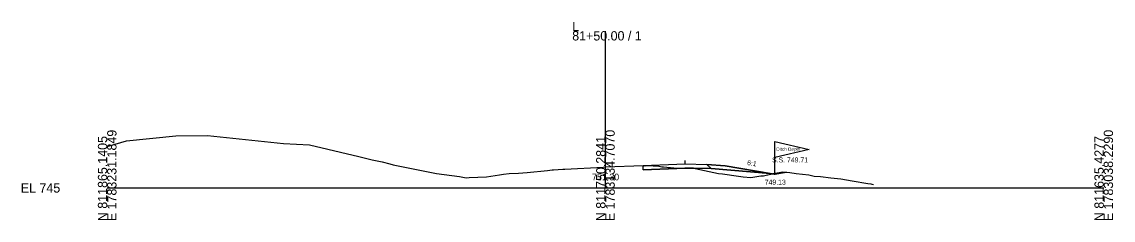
# Model space of a CAD drawing. Extents: x -26 to 7903, y -10 to 9573.
# Drawn here: x 4974.3 to 5302.8, y 2490.3 to 2549.9 of the extents above; entities that cross this region are included whole.
import ezdxf

# ---------------------------------------------------------------- set-up
doc = ezdxf.new("R2010")
doc.units = 0
for name, color, linetype in [('Exist Cross Section Cell', 7, 'Continuous'), ('Exist XS Center Line Elevation Label', 7, 'Continuous'), ('Exist XS Ground Line', 7, 'Continuous'), ('Prop XS Ditch Slope Text', 7, 'Continuous'), ('Prop XS Ditch Standard Text', 7, 'Continuous'), ('Prop XS Dump Level', 7, 'Continuous'), ('Prop XS Earthwork Shape', 7, 'Continuous'), ('Prop XS EOT Tick Mark', 7, 'Continuous'), ('Prop XS Finish Grade', 7, 'Continuous'), ('Prop XS Finish Grade Earthwork', 7, 'Continuous'), ('Prop XS Finish Grade Paved Shoulder', 7, 'Continuous'), ('Prop XS Finish Grade Pavement', 7, 'Continuous'), ('Prop XS Pvmt Edge Slope', 7, 'Continuous'), ('Prop XS SS Elevation Text', 7, 'Continuous'), ('Prop XS Subgrade Earthwork', 7, 'Continuous'), ('Scratch_Level_3', 7, 'Continuous'), ('Scratch_Level_6', 7, 'Continuous')]:
    doc.layers.add(name, color=color, linetype=linetype)

msp = doc.modelspace()

# ---------------------------------------------------------------- linework, layer by layer
at = {"layer": 'Exist Cross Section Cell'}
for p, q in [((5150, 2500), (5150, 2547.13)), ((5000, 2500), (5150, 2500)), ((5150, 2500), (5300, 2500))]:
    msp.add_line(p, q, dxfattribs=at)
at = {"layer": 'Exist XS Ground Line'}
for p, q in [((5000, 2512.48), (5005.78, 2514.17)), ((5005.78, 2514.17), (5020.7, 2515.66)), ((5020.7, 2515.66), (5030.17, 2515.71)), ((5030.17, 2515.71), (5053.1, 2513.32)), ((5053.1, 2513.32), (5060.88, 2512.97)), ((5060.88, 2512.97), (5075.72, 2509.42)), ((5075.72, 2509.42), (5079.79, 2508.47)), ((5079.79, 2508.47), (5082.83, 2507.82)), ((5082.83, 2507.82), (5085.06, 2507.24)), ((5085.06, 2507.24), (5086.05, 2506.96)), ((5086.05, 2506.96), (5099.09, 2504.37)), ((5150, 2506.3), (5161.31, 2506.73)), ((5161.31, 2506.73), (5164.32, 2506.68)), ((5099.09, 2504.37), (5106.08, 2503.41)), ((5114.15, 2503.37), (5118.11, 2503.96)), ((5118.11, 2503.96), (5119.31, 2504.18)), ((5119.31, 2504.18), (5120.98, 2504.3)), ((5120.98, 2504.3), (5123.87, 2504.46)), ((5123.87, 2504.46), (5126.42, 2504.6)), ((5126.42, 2504.6), (5132.51, 2505.24)), ((5132.51, 2505.24), (5133.96, 2505.4)), ((5133.96, 2505.4), (5134.36, 2505.43)), ((5134.36, 2505.43), (5137.13, 2505.6)), ((5137.13, 2505.6), (5137.74, 2505.63)), ((5137.74, 2505.63), (5149.28, 2506.27)), ((5149.28, 2506.27), (5150, 2506.3)), ((5164.32, 2506.68), (5165.35, 2506.66)), ((5165.35, 2506.66), (5165.7, 2506.59)), ((5165.7, 2506.59), (5167.02, 2506.33)), ((5167.02, 2506.33), (5167.46, 2506.3)), ((5167.46, 2506.3), (5170.55, 2506.07)), ((5170.55, 2506.07), (5172.27, 2505.98)), ((5172.27, 2505.98), (5176.07, 2505.9)), ((5176.07, 2505.9), (5176.46, 2505.91)), ((5176.46, 2505.91), (5177.05, 2505.79)), ((5177.05, 2505.79), (5184.07, 2504.38)), ((5184.07, 2504.38), (5185.19, 2504.22)), ((5185.19, 2504.22), (5190.03, 2503.56)), ((5190.03, 2503.56), (5191.44, 2503.33)), ((5193.78, 2503.11), (5196.79, 2503.62)), ((5196.79, 2503.62), (5197.56, 2503.63)), ((5197.56, 2503.63), (5198.38, 2503.8)), ((5198.38, 2503.8), (5200.6, 2504.34)), ((5200.6, 2504.34), (5203.38, 2504.8)), ((5203.38, 2504.8), (5205.53, 2504.62)), ((5205.53, 2504.62), (5207.36, 2504.37)), ((5207.36, 2504.37), (5211.26, 2503.97)), ((5211.26, 2503.97), (5212.79, 2503.52)), ((5212.79, 2503.52), (5214.72, 2503.45)), ((5214.72, 2503.45), (5217.87, 2503)), ((5106.08, 2503.41), (5108.07, 2503.05)), ((5108.07, 2503.05), (5108.94, 2503.09)), ((5108.94, 2503.09), (5114.15, 2503.37)), ((5191.44, 2503.33), (5193.78, 2503.11)), ((5217.87, 2503), (5220.84, 2502.68)), ((5220.84, 2502.68), (5224.31, 2502.08)), ((5224.31, 2502.08), (5228.97, 2501.34)), ((5228.97, 2501.34), (5229.93, 2501.19)), ((5229.93, 2501.19), (5230.23, 2501.14)), ((5230.23, 2501.14), (5230.66, 2501.07))]:
    msp.add_line(p, q, dxfattribs=at)
at = {"layer": 'Prop XS Dump Level'}
for p, q in [((5201, 2509.18), (5201, 2513.98)), ((5201, 2513.98), (5211.3, 2511.58)), ((5211.3, 2511.58), (5201, 2509.18)), ((5161.36, 2506.75), (5174, 2507.26)), ((5201, 2503.98), (5201, 2509.18))]:
    msp.add_line(p, q, dxfattribs=at)
at = {"layer": 'Prop XS Earthwork Shape'}
for points in [[(5170.55, 2506.07), (5172.27, 2505.98), (5173.93, 2505.94), (5161.32, 2505.48), (5161.32, 2506.73), (5164.32, 2506.68), (5165.35, 2506.66), (5165.7, 2506.59), (5167.02, 2506.33), (5167.46, 2506.3)], [(5173.93, 2505.94), (5176.07, 2505.9), (5176.28, 2505.9), (5174.01, 2505.95)], [(5176.46, 2505.91), (5176.5, 2505.9), (5176.28, 2505.9)], [(5176.5, 2505.9), (5177.05, 2505.79), (5184.07, 2504.38), (5185.19, 2504.22), (5190.03, 2503.56), (5191.44, 2503.33), (5193.78, 2503.11), (5196.79, 2503.62), (5197.56, 2503.63), (5198.38, 2503.8), (5200.26, 2504.25), (5199.54, 2504.37), (5181.81, 2505.79)], [(5200.6, 2504.34), (5203.38, 2504.8), (5204.49, 2504.71), (5201, 2504.13), (5200.26, 2504.25)]]:
    msp.add_lwpolyline(points, close=True, dxfattribs=at)
at = {"layer": 'Prop XS EOT Tick Mark'}
msp.add_line((5174, 2507.2), (5174, 2508.2), dxfattribs=at)
at = {"layer": 'Prop XS Finish Grade'}
for p, q in [((5180.53, 2507.07), (5186, 2506.63)), ((5186, 2506.63), (5199.54, 2504.37))]:
    msp.add_line(p, q, dxfattribs=at)
at = {"layer": 'Prop XS Finish Grade Earthwork'}
for p, q in [((5199.54, 2504.37), (5201, 2504.13)), ((5201, 2504.13), (5204.49, 2504.71))]:
    msp.add_line(p, q, dxfattribs=at)
at = {"layer": 'Prop XS Finish Grade Paved Shoulder'}
msp.add_line((5174, 2507.2), (5180.53, 2507.07), dxfattribs=at)
at = {"layer": 'Prop XS Finish Grade Pavement'}
msp.add_line((5161.32, 2506.73), (5174, 2507.2), dxfattribs=at)
at = {"layer": 'Prop XS Pvmt Edge Slope'}
msp.add_line((5180.53, 2507.07), (5181.81, 2505.79), dxfattribs=at)
at = {"layer": 'Prop XS Subgrade Earthwork'}
for p, q in [((5161.32, 2505.48), (5161.32, 2506.73)), ((5161.32, 2505.48), (5174.01, 2505.95)), ((5174.01, 2505.95), (5181.81, 2505.79)), ((5181.81, 2505.79), (5199.54, 2504.37))]:
    msp.add_line(p, q, dxfattribs=at)
at = {"layer": 'Scratch_Level_3'}
for p, q in [((5186, 2506.63), (5180.53, 2507.07)), ((5180.53, 2507.07), (5181.81, 2505.79)), ((5181.81, 2505.79), (5199.54, 2504.37)), ((5199.54, 2504.37), (5186, 2506.63))]:
    msp.add_line(p, q, dxfattribs=at)
at = {"layer": 'Scratch_Level_6'}
for points in [[(5167.46, 2506.3), (5170.55, 2506.07), (5172.27, 2505.98), (5173.93, 2505.94), (5161.32, 2505.48), (5161.32, 2506.73), (5164.32, 2506.68), (5165.35, 2506.66), (5165.7, 2506.59), (5167.02, 2506.33)], [(5176.28, 2505.9), (5176.5, 2505.9), (5176.46, 2505.91)]]:
    msp.add_lwpolyline(points, close=True, dxfattribs=at)

# ---------------------------------------------------------------- texts
at = {"layer": 'Exist Cross Section Cell'}
for s, p in [('L', (5140, 2547.13)), ('81+50.00 / 1', (5140, 2544.33)), ('EL 745', (4974, 2498.6))]:
    msp.add_text(s, height=2.8, dxfattribs=at).set_placement(p)
for s, p in [('E 1783231.1849', (5002.8, 2490)), ('E 1783134.7070', (5152.8, 2490)), ('E 1783038.2290', (5302.8, 2490)), ('N 811865.1405', (5000, 2490)), ('N 811750.2841', (5150, 2490)), ('N 811635.4277', (5300, 2490))]:
    msp.add_text(s, height=2.8, rotation=90, dxfattribs=at).set_placement(p)
at = {"layer": 'Exist XS Center Line Elevation Label'}
msp.add_text('751.30', height=2, dxfattribs=at).set_placement((5145.95, 2502.3))
at = {"layer": 'Prop XS Ditch Slope Text'}
msp.add_text('6:1', height=1.5, rotation=350.5377, dxfattribs=at).set_placement((5192.55, 2506.91))
at = {"layer": 'Prop XS Ditch Standard Text'}
msp.add_text('749.13', height=1.5, dxfattribs=at).set_placement((5197.95, 2500.98))
at = {"layer": 'Prop XS Dump Level'}
for s, height, p in [('Ditch Depth', 1, (5201.44, 2511.15)), ('Eop', 0.3, (5161.32, 2506.43)), ('Case4', 0.04, (5186, 2506.44))]:
    msp.add_text(s, height=height, dxfattribs=at).set_placement(p)
at = {"layer": 'Prop XS SS Elevation Text'}
msp.add_text('S.S. 749.71', height=1.5, dxfattribs=at).set_placement((5200.16, 2507.66))

doc.saveas('drawing.dxf')
